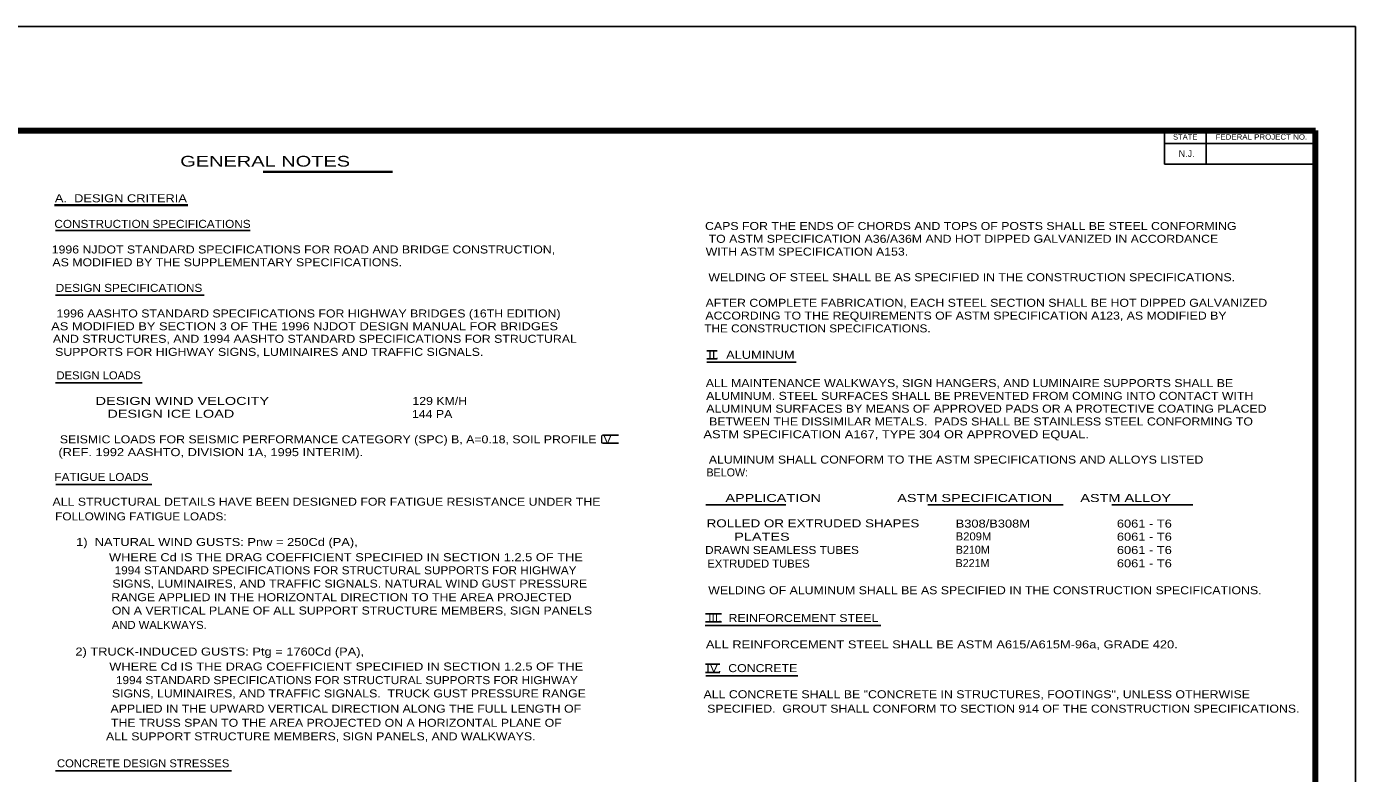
# Model space of a CAD drawing. Extents: x 312601.858 to 312602.699, y 144420.109 to 144420.704.
# Drawn here: x 312602.2008 to 312602.6988, y 144420.4234 to 144420.7035 of the extents above; entities that cross this region are included whole.
import ezdxf
from ezdxf.enums import TextEntityAlignment as Align

# ---------------------------------------------------------------- set-up
doc = ezdxf.new("R2010")
doc.units = 0
doc.header["$LTSCALE"] = 0.0012
for name, color, linetype, lineweight in [('1', 7, 'Continuous', 13), ('2', 7, 'Continuous', 25), ('39', 7, 'Continuous', 13), ('61', 7, 'Continuous', 25)]:
    doc.layers.add(name, color=color, linetype=linetype, lineweight=lineweight)

msp = doc.modelspace()

# ---------------------------------------------------------------- linework, layer by layer
at = {"layer": '2', "lineweight": 35}
for p, q in [((312602.2895, 144420.649), (312602.338, 144420.649)), ((312602.2113, 144420.6365), (312602.2612, 144420.6365))]:
    msp.add_line(p, q, dxfattribs=at)
at = {"layer": '2'}
for p, q in [((312602.2116, 144420.627), (312602.2846, 144420.627)), ((312602.2117, 144420.6028), (312602.2673, 144420.6028)), ((312602.4596, 144420.5819), (312602.4557, 144420.5819)), ((312602.4569, 144420.5819), (312602.4583, 144420.5819)), ((312602.4596, 144420.5789), (312602.4557, 144420.5789)), ((312602.4557, 144420.5776), (312602.4892, 144420.5776)), ((312602.457, 144420.5789), (312602.4583, 144420.5789)), ((312602.2117, 144420.5699), (312602.2441, 144420.5699)), ((312602.4226, 144420.5502), (312602.4166, 144420.5502)), ((312602.4226, 144420.5472), (312602.4166, 144420.5472)), ((312602.2118, 144420.5317), (312602.2477, 144420.5317)), ((312602.4553, 144420.5241), (312602.4853, 144420.5241)), ((312602.5385, 144420.5241), (312602.5893, 144420.5241)), ((312602.6075, 144420.5241), (312602.6379, 144420.5241)), ((312602.4603, 144420.4832), (312602.4552, 144420.4832)), ((312602.4566, 144420.4832), (312602.4612, 144420.4832)), ((312602.4551, 144420.4789), (312602.5209, 144420.4789)), ((312602.4612, 144420.4802), (312602.4552, 144420.4802)), ((312602.4567, 144420.4802), (312602.46, 144420.4802)), ((312602.4552, 144420.4644), (312602.4606, 144420.4644)), ((312602.4552, 144420.4612), (312602.4606, 144420.4612)), ((312602.4553, 144420.46), (312602.4898, 144420.46)), ((312602.2117, 144420.4244), (312602.2776, 144420.4244))]:
    msp.add_line(p, q, dxfattribs=at)
at = {"layer": '39', "lineweight": 25}
for p, q in [((312601.8578, 144420.7035), (312602.6988, 144420.7035)), ((312602.6988, 144420.1095), (312602.6988, 144420.7035)), ((312602.5735, 144420.6645), (312602.6838, 144420.6645))]:
    msp.add_line(p, q, dxfattribs=at)
at = {"layer": '39', "lineweight": 158}
for p in [(312601.9088, 144420.6645), (312602.6838, 144420.1247)]:
    msp.add_line(p, (312602.6838, 144420.6645), dxfattribs=at)
at = {"layer": '61'}
for p, q in [((312602.6273, 144420.6645), (312602.6273, 144420.6519)), ((312602.6429, 144420.6645), (312602.6429, 144420.6519)), ((312602.6838, 144420.6597), (312602.6273, 144420.6597)), ((312602.6838, 144420.6519), (312602.6273, 144420.6519))]:
    msp.add_line(p, q, dxfattribs=at)

# ---------------------------------------------------------------- texts
at = {"layer": '1'}
for s, width, p in [('B308/B308M', 1.2, (312602.549, 144420.5156)), ('6061 - T6', 1.2, (312602.6094, 144420.5156)), ('B209M', 1.05, (312602.549, 144420.5108)), ('6061 - T6', 1.2, (312602.6094, 144420.5107)), ('6061 - T6', 1.2, (312602.6094, 144420.5057)), ('6061 - T6', 1.2, (312602.6094, 144420.5007))]:
    msp.add_text(s, height=0.003, dxfattribs=dict(at, width=width)).set_placement(p)
at = {"layer": '2'}
for s, height, width, p in [('                         GENERAL NOTES', 0.004, 1.4, (312602.2642, 144420.651)), ('A.  DESIGN CRITERIA', 0.003, 1.2, (312602.23615, 144420.6376)), ('CONSTRUCTION SPECIFICATIONS', 0.003, 1.1, (312602.248, 144420.628)), ('CAPS FOR THE ENDS OF CHORDS AND TOPS OF POSTS SHALL BE STEEL CONFORMING ', 0.003, 1.15, (312602.5553, 144420.6272)), ('1996 NJDOT STANDARD SPECIFICATIONS FOR ROAD AND BRIDGE CONSTRUCTION,', 0.003, 1.15, (312602.30455, 144420.6184)), ('TO ASTM SPECIFICATION A36/A36M AND HOT DIPPED GALVANIZED IN ACCORDANCE', 0.003, 1.15, (312602.5519, 144420.6224)), (' AS MODIFIED BY THE SUPPLEMENTARY SPECIFICATIONS.', 0.003, 1.15, (312602.27535, 144420.6136)), ('WITH ASTM SPECIFICATION A153.', 0.003, 1.15, (312602.49325, 144420.6176)), ('WELDING OF STEEL SHALL BE AS SPECIFIED IN THE CONSTRUCTION SPECIFICATIONS. ', 0.003, 1.15, (312602.55565, 144420.608)), ('DESIGN SPECIFICATIONS', 0.003, 1.1, (312602.2392, 144420.604)), ('AFTER COMPLETE FABRICATION, EACH STEEL SECTION SHALL BE HOT DIPPED GALVANIZED', 0.003, 1.15, (312602.5605, 144420.5984)), ('1996 AASHTO STANDARD SPECIFICATIONS FOR HIGHWAY BRIDGES (16TH EDITION)', 0.003, 1.15, (312602.30645, 144420.5944)), ('ACCORDING TO THE REQUIREMENTS OF ASTM SPECIFICATION A123, AS MODIFIED BY', 0.003, 1.15, (312602.55285, 144420.5936)), ('AS MODIFIED BY SECTION 3 OF THE 1996 NJDOT DESIGN MANUAL FOR BRIDGES', 0.003, 1.2, (312602.305, 144420.5896)), ('THE CONSTRUCTION SPECIFICATIONS.', 0.003, 1.1, (312602.4972, 144420.5888)), ('AND STRUCTURES, AND 1994 AASHTO STANDARD SPECIFICATIONS FOR STRUCTURAL', 0.003, 1.15, (312602.30885, 144420.5849)), ('SUPPORTS FOR HIGHWAY SIGNS, LUMINAIRES AND TRAFFIC SIGNALS.', 0.003, 1.15, (312602.29175, 144420.58)), ('II.  ALUMINUM', 0.003, 1.2, (312602.47245, 144420.5789)), ('DESIGN LOADS', 0.003, 1.05, (312602.2278, 144420.5712)), ('ALL MAINTENANCE WALKWAYS, SIGN HANGERS, AND LUMINAIRE SUPPORTS SHALL BE ', 0.003, 1.15, (312602.5548, 144420.5683)), ('ALUMINUM. STEEL SURFACES SHALL BE PREVENTED FROM COMING INTO CONTACT WITH ', 0.003, 1.15, (312602.55865, 144420.5635)), ('DESIGN WIND VELOCITY                              ', 0.003, 1.35, (312602.28175, 144420.5616)), ('129 KM/H', 0.003, 1.15, (312602.35565, 144420.5616)), ('ALUMINUM SURFACES BY MEANS OF APPROVED PADS OR A PROTECTIVE COATING PLACED ', 0.003, 1.15, (312602.56115, 144420.5587)), ('DESIGN ICE LOAD                                   ', 0.003, 1.35, (312602.2812, 144420.5568)), ('144 PA', 0.003, 1.15, (312602.3528, 144420.5567)), ('BETWEEN THE DISSIMILAR METALS.  PADS SHALL BE STAINLESS STEEL CONFORMING TO', 0.003, 1.15, (312602.5585, 144420.5539)), ('ASTM SPECIFICATION A167, TYPE 304 OR APPROVED EQUAL.', 0.003, 1.2, (312602.5267, 144420.5491)), ('SEISMIC LOADS FOR SEISMIC PERFORMANCE CATEGORY (SPC) B, A=0.18, SOIL PROFILE IV', 0.003, 1.15, (312602.31665, 144420.5472)), ('(REF. 1992 AASHTO, DIVISION 1A, 1995 INTERIM).', 0.003, 1.2, (312602.26985, 144420.5424)), ('ALUMINUM SHALL CONFORM TO THE ASTM SPECIFICATIONS AND ALLOYS LISTED', 0.003, 1.15, (312602.54915, 144420.5396)), ('FATIGUE LOADS', 0.003, 1.1, (312602.2289, 144420.5331)), ('ALL STRUCTURAL DETAILS HAVE BEEN DESIGNED FOR FATIGUE RESISTANCE UNDER THE', 0.003, 1.15, (312602.3132, 144420.5238)), ('APPLICATION                   ASTM SPECIFICATION       ASTM ALLOY', 0.003, 1.35, (312602.5462, 144420.5252)), ('FOLLOWING FATIGUE LOADS:', 0.003, 1.1, (312602.24365, 144420.5183)), ('ROLLED OR EXTRUDED SHAPES       ', 0.003, 1.25, (312602.5004, 144420.5157)), ('1)  NATURAL WIND GUSTS: Pnw = 250Cd (PA),', 0.003, 1.2, (312602.27215, 144420.5087)), ('PLATES                   ', 0.003, 1.35, (312602.4907, 144420.5107)), ('DRAWN SEAMLESS TUBES', 0.003, 1.1, (312602.4839, 144420.5057)), ('WHERE Cd IS THE DRAG COEFFICIENT SPECIFIED IN SECTION 1.2.5 OF THE', 0.003, 1.2, (312602.3205, 144420.503)), ('EXTRUDED TUBES', 0.003, 1.05, (312602.4751, 144420.5006)), ('1994 STANDARD SPECIFICATIONS FOR STRUCTURAL SUPPORTS FOR HIGHWAY', 0.003, 1.1, (312602.32035, 144420.4981)), ('SIGNS, LUMINAIRES, AND TRAFFIC SIGNALS. NATURAL WIND GUST PRESSURE', 0.003, 1.15, (312602.3219, 144420.4931)), ('WELDING OF ALUMINUM SHALL BE AS SPECIFIED IN THE CONSTRUCTION SPECIFICATIONS.', 0.003, 1.15, (312602.55995, 144420.4906)), ('RANGE APPLIED IN THE HORIZONTAL DIRECTION TO THE AREA PROJECTED', 0.003, 1.15, (312602.3188, 144420.488)), ('ON A VERTICAL PLANE OF ALL SUPPORT STRUCTURE MEMBERS, SIGN PANELS', 0.003, 1.15, (312602.32275, 144420.483)), ('III.  REINFORCEMENT STEEL', 0.003, 1.15, (312602.4881, 144420.4802)), ('AND WALKWAYS.', 0.003, 1.05, (312602.25055, 144420.4776)), ('ALL REINFORCEMENT STEEL SHALL BE ASTM A615/A615M-96a, GRADE 420.', 0.003, 1.2, (312602.5438, 144420.4703)), ('2) TRUCK-INDUCED GUSTS: Ptg = 1760Cd (PA),', 0.003, 1.2, (312602.2732, 144420.4676)), ('WHERE Cd IS THE DRAG COEFFICIENT SPECIFIED IN SECTION 1.2.5 OF THE', 0.003, 1.2, (312602.3206, 144420.462)), ('IV.  CONCRETE', 0.003, 1.15, (312602.4726, 144420.4614)), ('1994 STANDARD SPECIFICATIONS FOR STRUCTURAL SUPPORTS FOR HIGHWAY', 0.003, 1.1, (312602.32085, 144420.4569)), ('SIGNS, LUMINAIRES, AND TRAFFIC SIGNALS.  TRUCK GUST PRESSURE RANGE', 0.003, 1.15, (312602.3216, 144420.4519)), ('ALL CONCRETE SHALL BE "CONCRETE IN STRUCTURES, FOOTINGS", UNLESS OTHERWISE', 0.003, 1.15, (312602.5569, 144420.4516)), ('APPLIED IN THE UPWARD VERTICAL DIRECTION ALONG THE FULL LENGTH OF', 0.003, 1.15, (312602.32045, 144420.4462)), ('SPECIFIED.  GROUT SHALL CONFORM TO SECTION 914 OF THE CONSTRUCTION SPECIFICATIONS.', 0.003, 1.15, (312602.56685, 144420.4462)), ('THE TRUSS SPAN TO THE AREA PROJECTED ON A HORIZONTAL PLANE OF', 0.003, 1.15, (312602.3169, 144420.4409)), ('ALL SUPPORT STRUCTURE MEMBERS, SIGN PANELS, AND WALKWAYS.', 0.003, 1.15, (312602.31105, 144420.4358)), ('CONCRETE DESIGN STRESSES', 0.003, 1.05, (312602.2445, 144420.4257))]:
    msp.add_text(s, height=height, dxfattribs=dict(at, width=width)).set_placement(p, align=Align.CENTER)
for s, p in [('BELOW:', (312602.4634, 144420.5348)), ('B210M', (312602.5554, 144420.5058)), ('B221M', (312602.5553, 144420.5008))]:
    msp.add_text(s, height=0.003, dxfattribs=at).set_placement(p, align=Align.CENTER)
at = {"layer": '61'}
for s, width, p in [('STATE', 1.05, (312602.635, 144420.6611)), ('FEDERAL PROJECT NO.', 1.1, (312602.66355, 144420.6611))]:
    msp.add_text(s, height=0.00201, dxfattribs=dict(at, width=width)).set_placement(p, align=Align.CENTER)
msp.add_text('N.J.', height=0.002512, dxfattribs=at).set_placement((312602.63555, 144420.6546), align=Align.CENTER)

doc.saveas('drawing.dxf')
